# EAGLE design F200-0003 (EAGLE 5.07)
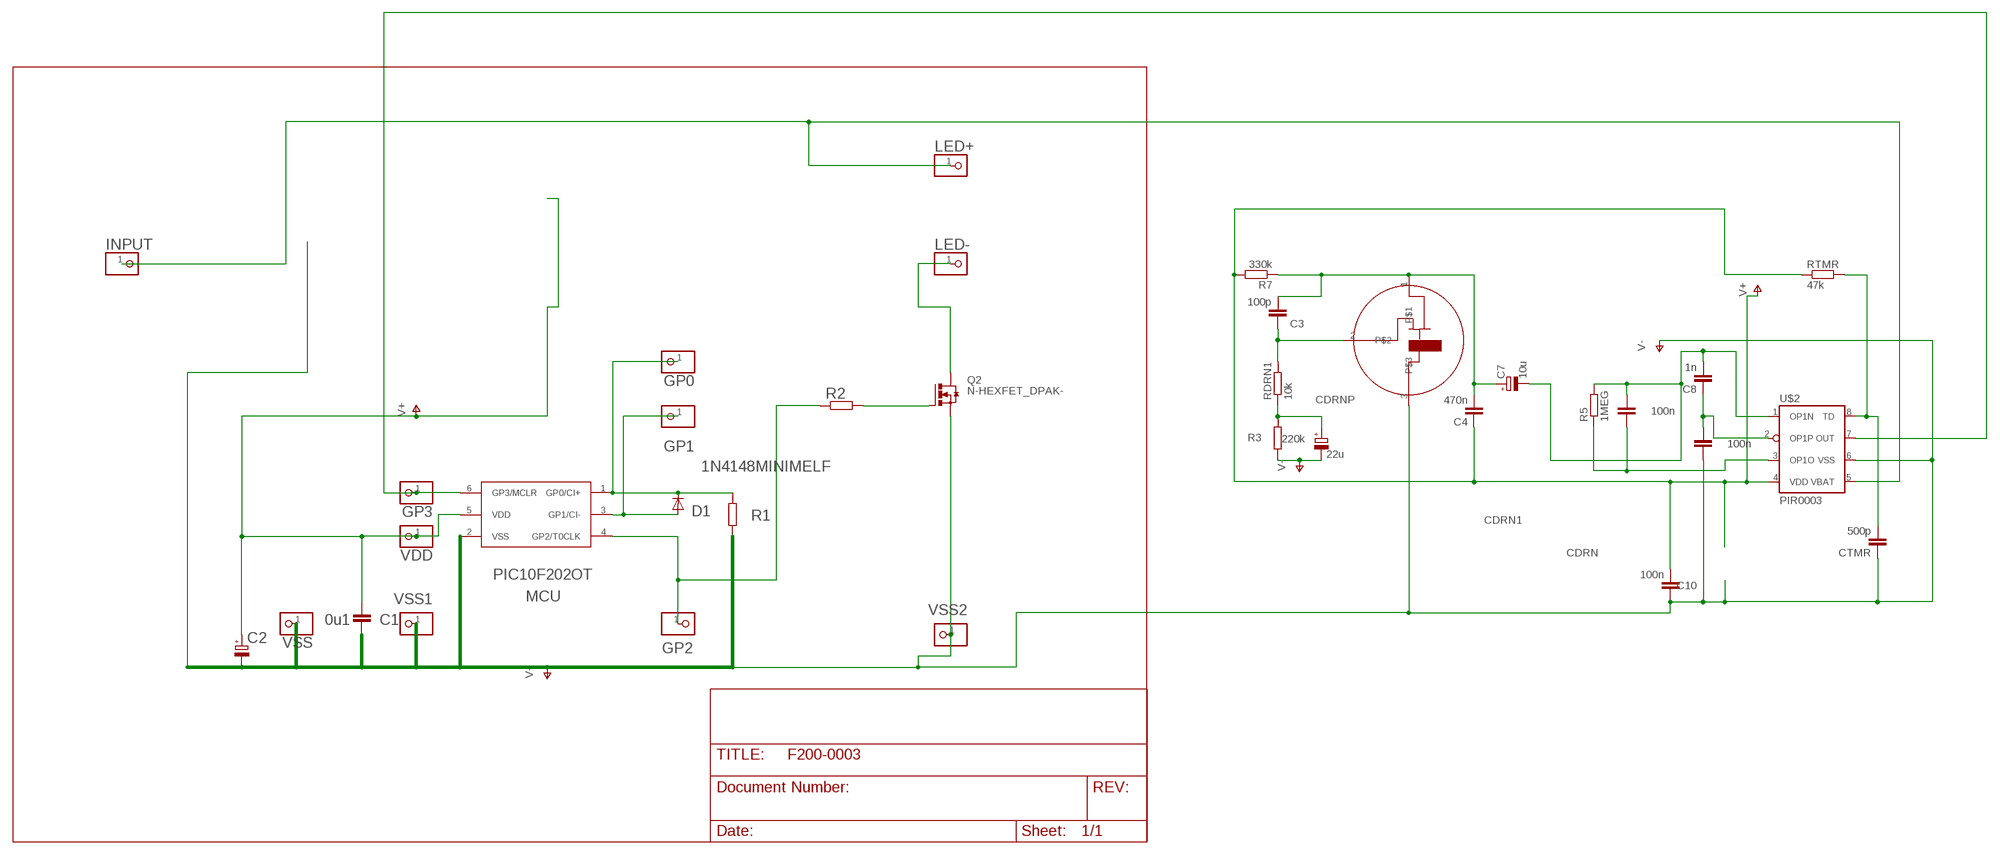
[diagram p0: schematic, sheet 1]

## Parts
C1  0u1  C-EUC1206  [C1206]
C2  CPOL-EUSMCB  [SMC_B]
C3  100p  C-EUC0805  [C0805]
C4  470n  C-EUC0805  [C0805]
C7  10u  CPOL-EUSMCA  [SMC_A]
C8  1n  C-EUC0805  [C0805]
C10  100n  C-EUC1206  [C1206]
CDRN  100n  C-EUC0805  [C0805]
CDRN1  100n  C-EUC0805  [C0805]
CDRNP  22u  CPOL-EUSMCB  [SMC_B]
CTMR  500p  C-EUC0805  [C0805]
D1  1N4148MINIMELF  [MINIMELF]
GP0  PINHD-1X1  [1X01]
GP1  PINHD-1X1  [1X01]
GP2  PINHD-1X1  [1X01]
GP3  PINHD-1X1  [1X01]
INPUT  PINHD-1X1  [1X01]
LED+  PINHD-1X1  [1X01]
LED-  PINHD-1X1  [1X01]
MCU  PIC10F202OT  [SOT23-6]
PIR  RE200B  [R200B]
Q2  N-HEXFET_DPAK-  [TO252]
R1  R-EU_R0805  [R0805]
R2  R-EU_R0805  [R0805]
R3  220k  R-EU_R0805  [R0805]
R5  1MEG  R-EU_R0805  [R0805]
R7  330k  R-EU_R0805  [R0805]
RDRN1  10k  R-EU_R0805  [R0805]
RTMR  47k  R-EU_R0805  [R0805]
U$2  PIR0003  [SO08]
VDD  PINHD-1X1  [1X01]
VSS  PINHD-1X1  [1X01]
VSS1  PINHD-1X1  [1X01]
VSS2  PINHD-1X1  [1X01]

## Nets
GP0: D1.C GP0.1 MCU.1(GP0/CI+) R1.2
GP1: D1.A GP1.1 MCU.3(GP1/CI-)
GP2: GP2.1 MCU.4(GP2/T0CLK) R2.1
GP3: GP3.1 MCU.6(GP3/MCLR) U$2.7(OUT)
HOT: LED-.1 Q2.3(D)
N$1: C3.1 PIR.2 RDRN1.2
N$3: Q2.1(G) R2.2
N$4: C3.2 C4.2 C7.+ PIR.1 R7.1
N$7: CDRNP.+ R3.2 RDRN1.1
N$8: C7.- C8.2 CDRN1.2 R5.2 U$2.1(OP1N)
N$9: C8.1 CDRN.2 U$2.2(OP1P)
N$11: CDRN1.1 R5.1 U$2.3(OP1O)
N$12: CTMR.2 RTMR.2 U$2.8(TD)
V5: INPUT.1 LED+.1 U$2.5(VBAT)
V+: C1.2 C2.+ C4.1 C10.2 MCU.5(VDD) R7.2 RTMR.1 U$2.4(VDD) VDD.1
V-: C1.1 C2.- C10.1 CDRN.1 CDRNP.- CTMR.1 MCU.2(VSS) PIR.3 Q2.2(S) R1.1 R3.1 U$2.6(VSS) VSS1.1 VSS2.1 VSS.1

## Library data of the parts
C1 C3 C4 C8 C10 CDRN CDRN1 CTMR = rcl:C-EU: CAPACITOR, European symbol
C2 = rcl-2:CPOL-EU: POLARIZED CAPACITOR, European symbol
C7 CDRNP = rcl:CPOL-EU: POLARIZED CAPACITOR, European symbol
D1 = diode-1:1N4148: DIODE
GP0 GP1-GP3 INPUT LED+ LED- VDD VSS VSS1 VSS2 = pinhead(2):PINHD-1X1: PIN HEADER
MCU = microchip-3:PIC10F2*: uPC nW 0,25/0,5k Program Flash memory Comparator
PIR = photo-elements:RE200B
Q2 = transistor-power:N-HEXFET_?-*: HEXFET® Power MOSFET
R1 R2 = rcl-2:R-EU_: RESISTOR, European symbol
R3 R5 R7 RDRN1 RTMR = rcl:R-EU_: RESISTOR, European symbol
U$2 = linear:PIR0003

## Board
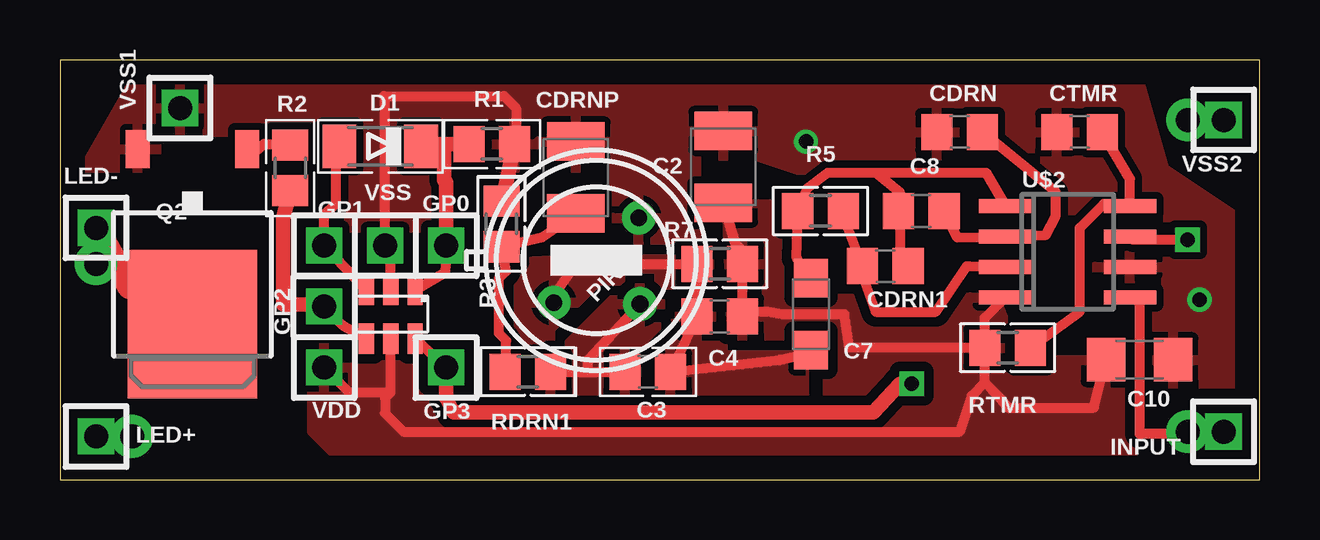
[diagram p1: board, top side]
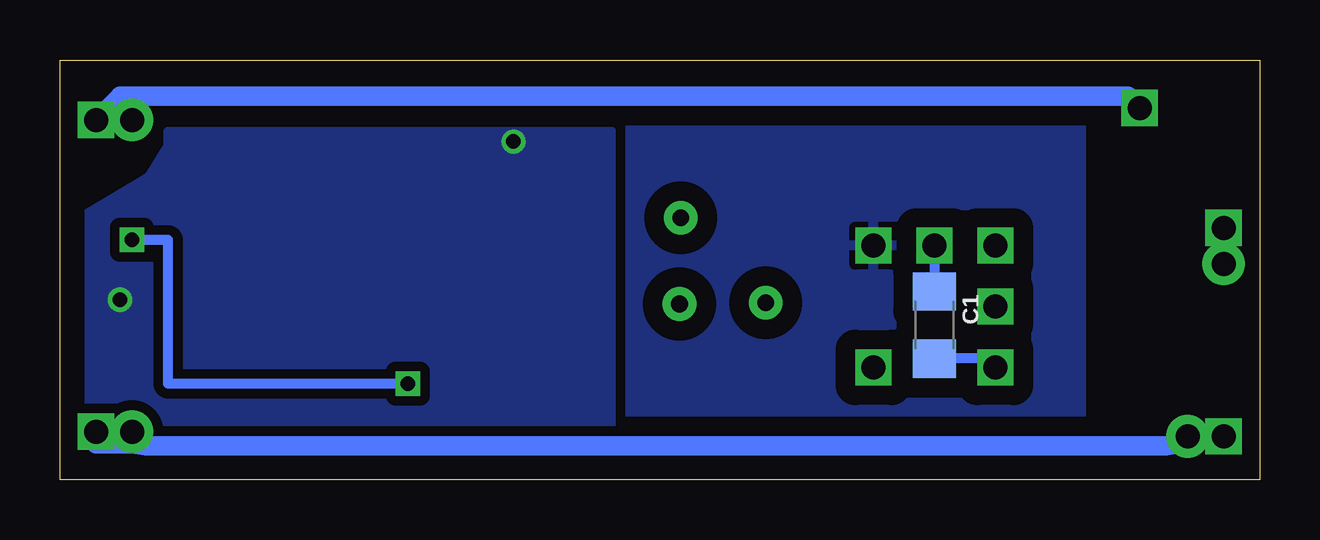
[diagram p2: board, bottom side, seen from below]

Size 50 x 17.5 mm. Coordinates in mm from the lower left corner, seen from the top.
Outline: 0,0 50,0 50,17.5 0,17.5 0,0
Copper layers (1*16): Top 0.035mm / dielectric 1.5mm / Bottom 0.035mm
Design rules "default": minimum track width 10mil, minimum drill 24mil, track to track 8mil, track to pad 8mil, pad to pad 8mil, via to via 8mil, smd to smd 8mil, copper to edge 40mil, drill to drill 8mil, minimum pad ring 10mil, minimum via ring 8mil, stop-mask expansion 4mil, vias tented up to drill 0mil, thermal gap 10mil

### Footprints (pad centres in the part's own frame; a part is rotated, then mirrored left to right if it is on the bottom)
C1206 = smd 1.6 x 1.8: 1 -1.4,0; 2 1.4,0
SMC_B = smd 1.6 x 2.4: + -1.5,0; - 1.5,0
C0805 = smd 1.3 x 1.5: 1 -0.95,0; 2 0.95,0
SMC_A = smd 1.6 x 1.4: + -1.5,0; - 1.5,0
MINIMELF = smd 1.4 x 1.8: A 1.7,0; C -1.7,0
1X01 = drill 1 pad 1.27 square: 1 0,0
SOT23-6 = smd 0.635 x 1.27: 1 -1.016,-1.016; 2 0,-1.016; 3 1.016,-1.016; 4 1.016,1.016; 5 0,1.016; 6 -1.016,1.016
R200B = drill 0.7 pad 1.4 round: 1 -2.5,0; 2 0,-2.58; 3 2.5,0
TO252 = smd 1 x 1.6: 1 -2.28,-3.53; 2 2.28,-3.53 | smd 5.4 x 6.2: 3 0,3.77
R0805 = smd 1.3 x 1.5: 1 -0.95,0; 2 0.95,0
SO08 = smd 0.6 x 2.2: 1 -1.905,-2.6; 2 -0.635,-2.6; 3 0.635,-2.6; 4 1.905,-2.6; 5 1.905,2.6; 6 0.635,2.6; 7 -0.635,2.6; 8 -1.905,2.6

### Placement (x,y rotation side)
C1  13.55,6.45 270 bottom
C2  27.65,13.04 90 top
C3  24.5,4.5 0 top
C4  27.5,6.8 180 top
C7  31.3,6.9 90 top
C8  35.9,11.2 180 top
C10  45,5 180 top
CDRN  37.5,14.5 0 top
CDRN1  34.4,8.9 0 top
CDRNP  21.5,12.6 90 top
CTMR  42.5,14.5 0 top
D1  13.35,13.9 180 top
GP0  16.09,9.76 0 top
GP1  11.01,9.76 0 top
GP2  11.01,7.21 90 top
GP3  16.09,4.67 0 top
INPUT  48.5,2 90 top
LED+  1.5,1.8 0 top
LED-  1.5,10.5 0 top
MCU  13.79,6.9 180 top
PIR  22.35,9.15 45 top
Q2  5.52,10.25 180 top
R1  18,14 180 top
R2  9.6,13 90 top
R3  18.4,10.66 270 top
R5  31.7,11.2 180 top
R7  27.5,9 0 top
RDRN1  19.5,4.5 0 top
RTMR  39.5,5.5 0 top
U$2  42,9.5 270 top
VDD  11.01,4.67 0 top
VSS  13.55,9.76 0 top
VSS1  5,15.5 90 top
VSS2  48.5,15 0 top

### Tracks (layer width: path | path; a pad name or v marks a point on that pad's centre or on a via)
GP0
  Top 0.406: MCU.1 16.07,8.65 16.09,8.98 GP0.1 | 16.09,12.41 16,12.5 | D1.C 15.05,14
  Top 0.61: GP0.1 16.09,12.41 | 16,12.5 16,13.9 | 16,13.9 16,14 | 16,13.9 D1.C | 15.05,14 R1.2
  pour Bottom (isolate 0.813): 7.43,17.14 26.25,17.14 26.25,-0.64 7.43,-0.64
GP1
  Top 0.406: MCU.3 GP1.1 11.01,11.03 11.48,11.5 11.5,11.5 11.5,13.9 D1.A
GP2
  Top 0.406: MCU.4 11.79,6.43 GP2.1 10.8,7.3
  Top 0.61: R2.1 9.3,10.9 9.3,7.3 10.8,7.3
GP3  (via drill 0.6)
  Top 0.406: GP3.1 MCU.6 | v47,10 44.73,10 U$2.7
  Top 0.61: GP3.1 16.09,3.41 16.4,2.8 33.9,2.8 35,4 v35.5,4
  Bottom 0.406: v35.5,4 45.5,4 45.5,10 v47,10
HOT  (via drill 1 pad 1.78)
  Top 0.406: 2.9,8.04 Q2.3
  Top 1.016: LED-.1 2.9,8.04
  Bottom 0.406: v1.5,9 LED-.1
N$1
  Top 0.406: RDRN1.2 22,4.5 | 22,4.5 C3.1 | PIR.2 22,5 22,4.5
  pour Top (isolate 0.406, rank 2): 20,5 20.5,5 23.5,8 25,8 25,6.5 24,5.5 24,4 23.5,3.5 20,3.5
N$3
  Top 0.406: Q2.1 8.28,13.78 8.5,14 9.55,14 R2.2
N$4
  Top 0.406: C7.+ 31.3,5.3 30,5 C3.2 C4.2 R7.1 21.5,9 20.38,7.38 PIR.1
  pour Top (isolate 0.406, rank 4): 19.3,9.1 27,9.5 28,8.5 28,6.5 29,5.5 31,5.5 31,3 25.5,3 25,4 25,6.5 24,7.5 22.5,7.5 20.5,5.5 19,5.5 18.5,6 18.5,8
N$7
  Top 0.406: CDRNP.+ 20.11,10.11 R3.2 18.6,8.7 18.3,8.4 18.3,6.1 18.6,5.8 18.6,4.55 RDRN1.1
N$8
  Top 0.406: C7.- 30.7,9.25 R5.2 31.15,12.15 32,12.8 34,12.8 | 34,12.8 35,12 35,11.5 | 35,11.5 35,9.25 CDRN1.2 | U$2.1 38.6,12.8 34,12.8 | C8.2 34.95,11.45 35,11.5
N$9
  Top 0.406: C8.1 37.4,10.1 U$2.2 41.1,10.2 41.5,11 41.5,12 CDRN.2
N$11
  Top 0.406: R5.1 32.85,10.5 CDRN1.1 33.45,8.55 34,7 36.5,7 37.8,8.9 37.9,8.9 U$2.3
N$12
  Top 0.406: RTMR.2 42.5,7 42.5,10.5 43.5,11.5 U$2.8 44.6,12.55 CTMR.2
V5  (via drill 1 pad 1.78)
  Top 0.406: U$2.5 45,7.59 45,1.9 46.94,1.9 INPUT.1
  Bottom 0.406: INPUT.1 v47,2 | LED+.1 v3,1.8
  Bottom 0.813: LED+.1 3.9,1.4 46.4,1.4 47,1.5 48.5,1.5 INPUT.1
V+
  Top 0.406: 13.77,3.63 MCU.5 | 13.77,3.63 13.55,3.4 13.55,2.77 14.32,2 37.5,2 38,3.5 38.55,4.05 | RTMR.1 32.9,5.5 32.7,6.89 30.09,6.89 29.5,7 28.95,7 C4.1 R7.2 28.5,8.55 28.5,9.5 28.15,9.85 C2.+ | 38.55,4.05 RTMR.1 | 13.77,3.63 12.06,3.63 VDD.1 | C10.2 43.1,3 39.5,3 39.1,3.5 38.55,4.05 | RTMR.1 38.55,6.75 U$2.4
  Bottom 0.406: C1.2 11.64,5.04 VDD.1
  pour Top (isolate 0.406, rank 3): 10.5,5.5 14.5,5.5 15.5,4.5 15.5,3 32,3 32,6 28,6 27.8,11.5 30.5,11.5 30.5,7.5 38.9,7.8 40,5 45,5 45.5,4 45.5,1.5 44.5,0.5 12,0.5 10.5,2
V-  (via drill 0.6 pad 0.61, 1 pad 1.78)
  Top 0.254: VSS.1 13.75,9.32
  Top 0.406: 13.75,9.32 MCU.2 | VSS.1 13.55,15.95 13.5,16 18.5,16 19,15.5 19,14.52 R1.1 | 18.45,11.66 R3.1
  Top 0.61: R1.1 18.45,11.66
  Bottom 0.406: VSS.1 C1.1 | VSS2.1 v47,15
  Bottom 0.813: VSS2.1 47.5,16 5.5,16 VSS1.1
  other vias: 47.5,7.5 31.1,14.1
  pour Top (isolate 0.305, rank 2): 1,13 3,16.5 45,16.5 46,13 49,11 49,4 44.5,4 44.5,8 42.5,8 40.5,10 32,10 32,12.5 29,13.5 26.5,13.5 26.5,10 23,10 23,13 16.5,13 16.5,10.5 9,10.5 8.5,14.5 4,14.5 4,13
  pour Bottom (isolate 0.406, rank 2): 27,14.5 45.5,14.5 45.5,13.9 46.3,12.6 49,11 49,1.5 27,1.5

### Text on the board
tStop: MICHAEL5.net
bStop: MICHAEL5.net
